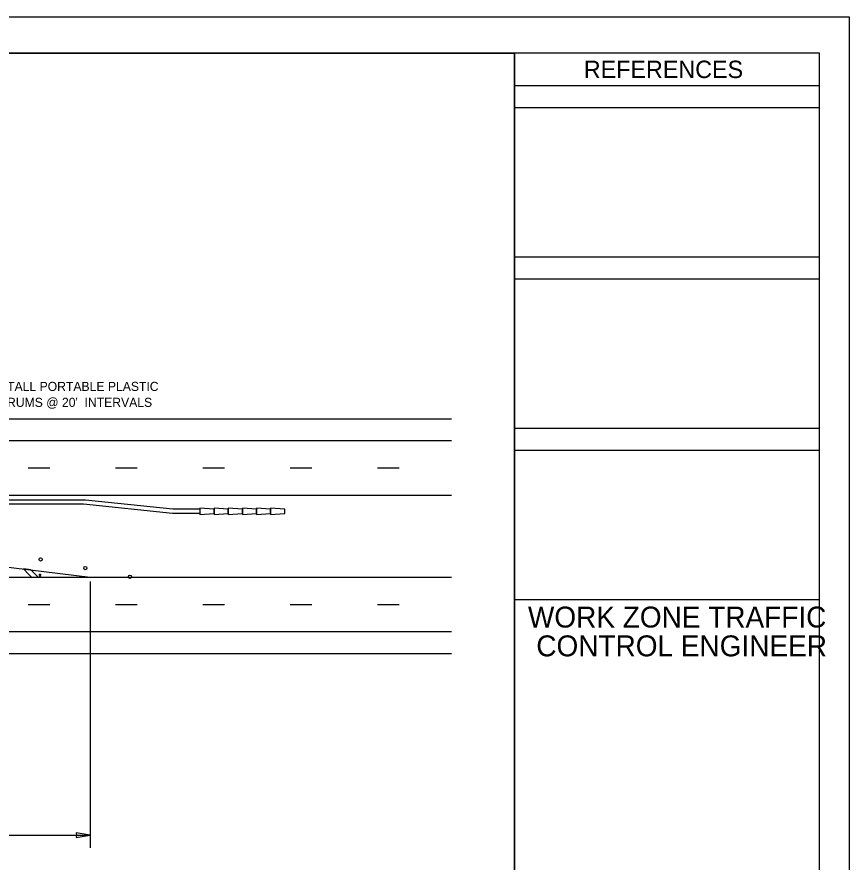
# Model space of a CAD drawing. Extents: x -2433 to -1135, y -5611 to -4633.
# Drawn here: x -1523.6 to -1157.6, y -5004.3 to -4632.8 of the extents above; entities that cross this region are included whole.
import ezdxf

# ---------------------------------------------------------------- set-up
doc = ezdxf.new("R2010")
doc.units = 0
for name, color, linetype in [('Level 42', 7, 'Continuous'), ('Level 45', 7, 'Continuous'), ('Level 46', 7, 'Continuous'), ('Level 48', 7, 'Continuous'), ('Level 49', 7, 'Continuous'), ('Level 50', 7, 'Continuous'), ('TR_WZ_TC_Edge Lines', 7, 'Continuous')]:
    doc.layers.add(name, color=color, linetype=linetype)

msp = doc.modelspace()

# ---------------------------------------------------------------- linework, layer by layer
at = {"layer": 'Level 42'}
for p, q in [((-1170.57, -4648.81), (-2364.77, -4648.78)), ((-1304.73, -5430.02), (-1304.73, -4648.85)), ((-1170.57, -5430.02), (-1170.57, -4648.81)), ((-1304.73, -4663.02), (-1170.72, -4663.02)), ((-1170.64, -4672.84), (-1304.73, -4672.84)), ((-1304.73, -4738.32), (-1170.72, -4738.32)), ((-1170.64, -4748.14), (-1304.73, -4748.14)), ((-1304.73, -4813.62), (-1170.72, -4813.62)), ((-1170.64, -4823.44), (-1304.73, -4823.44)), ((-1304.73, -4888.92), (-1170.57, -4888.92))]:
    msp.add_line(p, q, dxfattribs=at)
msp.add_lwpolyline([(-2364.77, -4648.78), (-1304.73, -4648.78), (-1304.73, -5430.02), (-2364.77, -5430.02)], close=True, dxfattribs=at)
at = {"layer": 'Level 45'}
for p, q in [((-1805.25, -4843.04), (-1332.46, -4843.04)), ((-1513.56, -4878.08), (-1513.56, -4877.76)), ((-1513.56, -4877.76), (-1513.24, -4877.76)), ((-1513.24, -4878.08), (-1513.56, -4878.08)), ((-1513.24, -4877.76), (-1513.24, -4878.08)), ((-1793.36, -4879.04), (-1332.46, -4879.04)), ((-1513.56, -4878.72), (-1513.56, -4878.4)), ((-1513.56, -4878.4), (-1513.24, -4878.4)), ((-1513.24, -4878.72), (-1513.56, -4878.72)), ((-1513.24, -4878.4), (-1513.24, -4878.72))]:
    msp.add_line(p, q, dxfattribs=at)
at = {"layer": 'Level 46'}
for p, q in [((-1800.24, -4809.44), (-1332.46, -4809.44)), ((-1800.24, -4819.04), (-1332.46, -4819.04)), ((-1518.61, -4831.04), (-1509.01, -4831.04)), ((-1480.21, -4831.04), (-1470.61, -4831.04)), ((-1441.81, -4831.04), (-1432.21, -4831.04)), ((-1403.41, -4831.04), (-1393.81, -4831.04)), ((-1365.01, -4831.04), (-1355.41, -4831.04)), ((-1491.33, -4881.06), (-1491.33, -4998.15)), ((-1518.61, -4891.04), (-1509.01, -4891.04)), ((-1480.21, -4891.04), (-1470.61, -4891.04)), ((-1441.81, -4891.04), (-1432.21, -4891.04)), ((-1403.41, -4891.04), (-1393.81, -4891.04)), ((-1365.01, -4891.04), (-1355.41, -4891.04)), ((-1800.24, -4903.04), (-1332.46, -4903.04)), ((-1800.24, -4912.64), (-1332.46, -4912.64)), ((-1800.24, -4992.52), (-1491.33, -4992.52))]:
    msp.add_line(p, q, dxfattribs=at)
at = {"layer": 'Level 48'}
for p, q in [((-1494.3, -4846.96), (-1809.17, -4846.96)), ((-1807.25, -4845.04), (-1493.44, -4845.04)), ((-1455.15, -4851.12), (-1494.3, -4846.96)), ((-1493.44, -4845.04), (-1455.04, -4849.12)), ((-1443.04, -4851.12), (-1455.15, -4851.12)), ((-1455.04, -4849.12), (-1443.04, -4849.12)), ((-1443.04, -4849.12), (-1443.04, -4851.12))]:
    msp.add_line(p, q, dxfattribs=at)
at = {"layer": 'Level 49'}
for p, q in [((-1491.33, -4992.52), (-1497.47, -4991.43)), ((-1497.47, -4991.43), (-1497.28, -4992.52)), ((-1497.28, -4992.52), (-1497.47, -4993.6)), ((-1497.47, -4993.6), (-1491.33, -4992.52))]:
    msp.add_line(p, q, dxfattribs=at)
at = {"layer": 'Level 50'}
for p, q in [((-1436.82, -4849.2), (-1443.04, -4848.72)), ((-1443.04, -4848.72), (-1443.04, -4851.6)), ((-1443.04, -4851.6), (-1436.82, -4851.12)), ((-1430.61, -4849.2), (-1436.82, -4848.72)), ((-1436.82, -4848.72), (-1436.82, -4851.6)), ((-1436.82, -4851.12), (-1436.82, -4849.2)), ((-1436.82, -4851.6), (-1430.61, -4851.12)), ((-1424.39, -4849.2), (-1430.61, -4848.72)), ((-1430.61, -4848.72), (-1430.61, -4851.6)), ((-1430.61, -4851.12), (-1430.61, -4849.2)), ((-1430.61, -4851.6), (-1424.39, -4851.12)), ((-1418.18, -4849.2), (-1424.39, -4848.72)), ((-1424.39, -4848.72), (-1424.39, -4851.6)), ((-1424.39, -4851.12), (-1424.39, -4849.2)), ((-1424.39, -4851.6), (-1418.18, -4851.12)), ((-1411.96, -4849.2), (-1418.18, -4848.72)), ((-1418.18, -4848.72), (-1418.18, -4851.6)), ((-1418.18, -4851.12), (-1418.18, -4849.2)), ((-1418.18, -4850.16), (-1418.18, -4850.16)), ((-1418.18, -4851.6), (-1411.96, -4851.12)), ((-1405.74, -4849.2), (-1411.96, -4848.72)), ((-1411.96, -4848.72), (-1411.96, -4851.6)), ((-1411.96, -4851.12), (-1411.96, -4849.2)), ((-1411.96, -4851.6), (-1405.74, -4851.12)), ((-1405.74, -4851.12), (-1405.74, -4849.2))]:
    msp.add_line(p, q, dxfattribs=at)
msp.add_lwpolyline([(-2432.94, -4632.82), (-1157.59, -4632.82), (-1157.59, -5447.91), (-2432.94, -5447.91)], close=True, dxfattribs=at)
for centre in [(-1513.1, -4871.31), (-1493.46, -4875.1), (-1473.83, -4878.9)]:
    msp.add_circle(centre, 0.72, dxfattribs=at)
at = {"layer": 'TR_WZ_TC_Edge Lines'}
for p, q in [((-1638.94, -4861.2), (-1491.33, -4879.04)), ((-1517.39, -4875.89), (-1520.61, -4875.5)), ((-1514.24, -4879.04), (-1517.39, -4875.89)), ((-1517.07, -4879.04), (-1514.24, -4879.04))]:
    msp.add_line(p, q, dxfattribs=at)
msp.add_lwpolyline([(-1520.61, -4875.5), (-1518.25, -4877.86), (-1517.07, -4879.04)], dxfattribs=at)

# ---------------------------------------------------------------- texts
at = {"layer": 'Level 42'}
for s, height, p in [('REFERENCES', 7.667, (-1274.26, -4659.71)), ('INSTALL PORTABLE PLASTIC', 4, (-1536.76, -4797.24)), ("DRUMS @ 20'  INTERVALS", 4, (-1531.75, -4804.24)), ('WORK ZONE TRAFFIC', 9.2, (-1298.82, -4901.24)), ('CONTROL ENGINEER', 9.2, (-1295.14, -4913.9))]:
    msp.add_text(s, height=height, dxfattribs=at).set_placement(p)

doc.saveas('drawing.dxf')
